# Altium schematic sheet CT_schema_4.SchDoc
size 235 x 277 mm
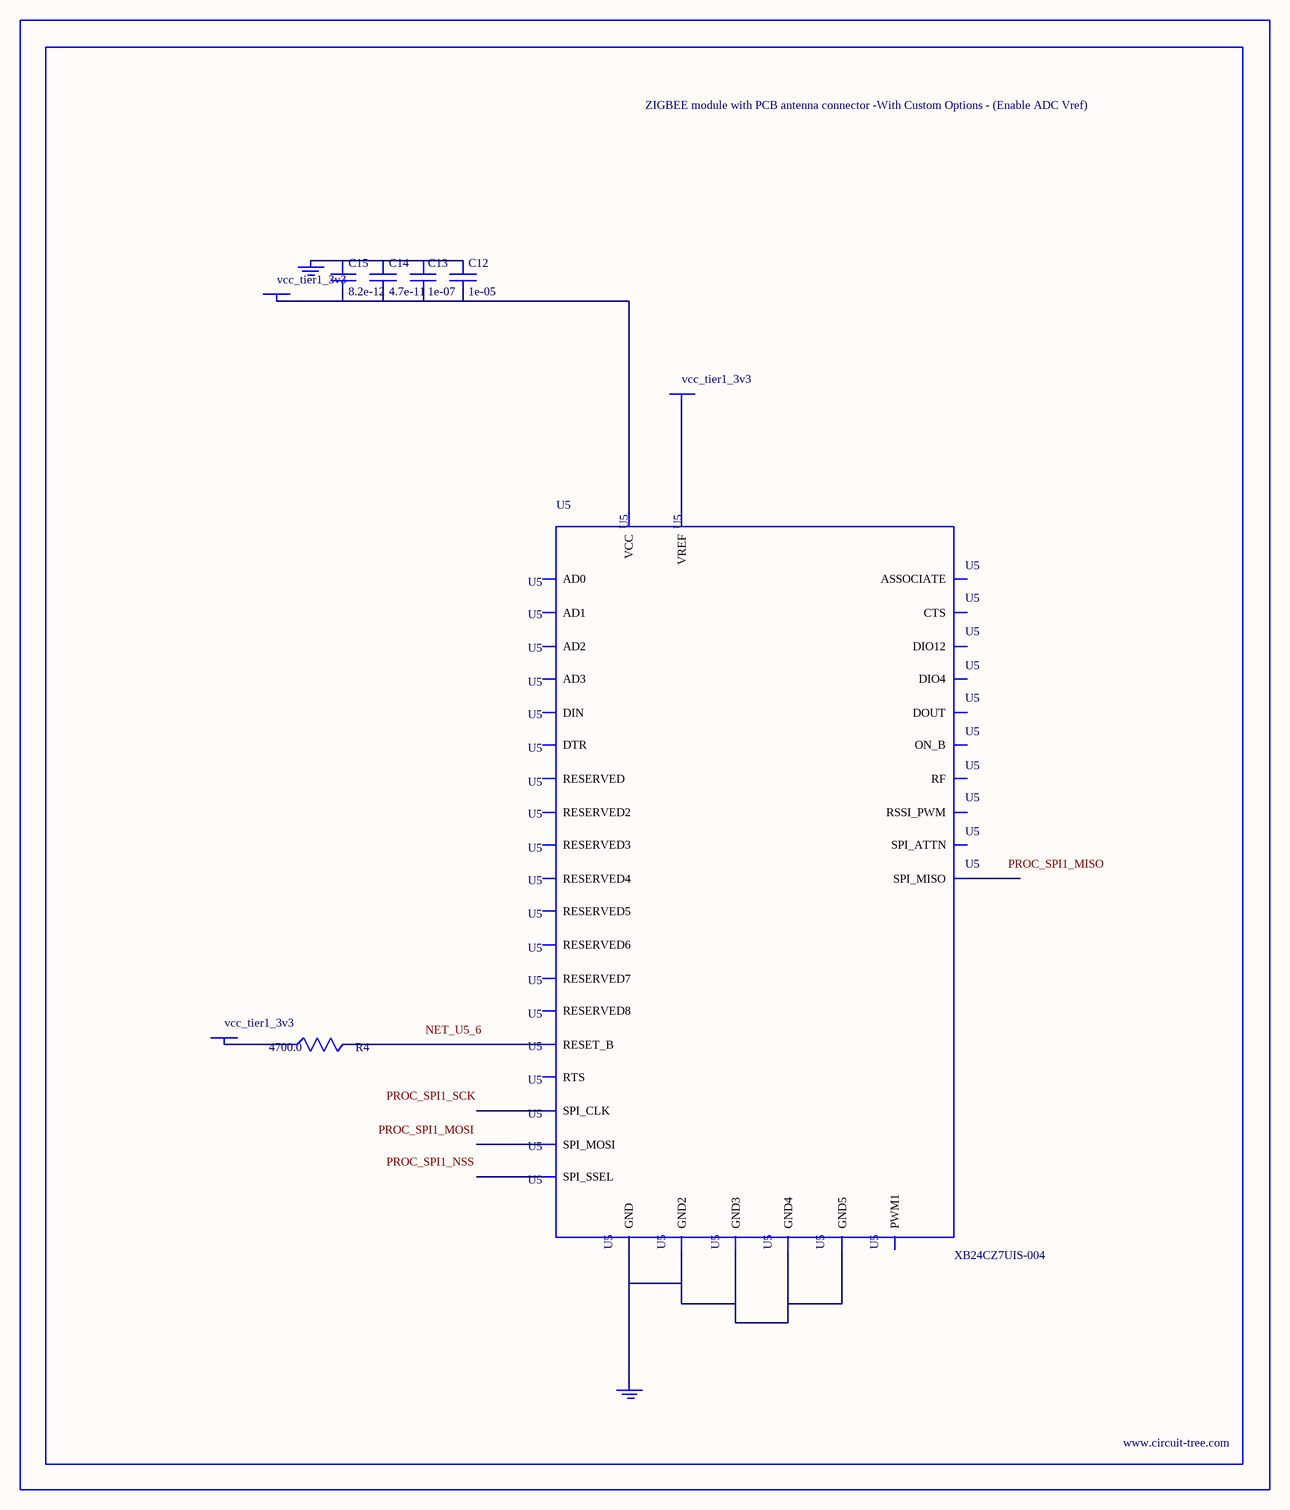
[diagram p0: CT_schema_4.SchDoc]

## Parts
BORDER3  (no value)
C12  1e-05  [C0805]
C13  1e-07  [C0402]
C14  4.7e-11  [C0402]
C15  8.2e-12  [C0603]
GND_INSTANCE_3_0  (no value)
GND_INSTANCE_3_1  (no value)
POWER_INSTANCE_3_0  vcc_tier1_3v3
POWER_INSTANCE_3_1  vcc_tier1_3v3
POWER_INSTANCE_3_2  vcc_tier1_3v3
R4  4700.0  [R0603]
U5  XB24CZ7UIS-004  [XB24CZ7UIS-004]

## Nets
NetC12_1: C12.1 C13.1 C14.1 C15.1 GND_INSTANCE_3_0.0(GND)
NetC12_2: C12.2 C13.2 C14.2 C15.2 POWER_INSTANCE_3_0.0(PWR) U5.2(VCC)
NetGND_INSTANCE_3_1_0: GND_INSTANCE_3_1.0(GND) U5.1(GND) U5.11(GND2) U5.13(GND3) U5.22(GND4) U5.35(GND5)
NetPOWER_INSTANCE_3_1_0: POWER_INSTANCE_3_1.0(PWR) R4.1
NetPOWER_INSTANCE_3_2_0: POWER_INSTANCE_3_2.0(PWR) U5.27(VREF)
NetR4_2: R4.2 U5.6(RESET_B)

Not connected (* = marked no-connect by the designer): U5 3(DOUT) 4(DIN) 5(DIO12) 7(RSSI_PWM) 8(PWM1) 9(RESERVED) 10(DTR) 12(SPI_ATTN) 14(SPI_CLK) 15(SPI_SSEL) 16(SPI_MOSI) 17(SPI_MISO) 18(RESERVED2) 19(RESERVED3) 20(RESERVED4) 21(RESERVED5) 23(RESERVED6) 24(DIO4) 25(CTS) 26(ON_B) 28(ASSOCIATE) 29(RTS) 30(AD3) 31(AD2) 32(AD1) 33(AD0) 34(RESERVED7) 36(RF) 37(RESERVED8)

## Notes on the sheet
- Labels drawn without touching a wire or pin: NET_U5_6, PROC_SPI1_MISO, PROC_SPI1_MOSI, PROC_SPI1_NSS, PROC_SPI1_SCK

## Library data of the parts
BORDER3 = BORDER_PAGE3
C12 = C0805C106K8RACTU
C13 = C0402C104K3RACTU
C14 = C0402C470K3RAC
C15 = 06035J8R2BBTTR
GND_INSTANCE_3_0 GND_INSTANCE_3_1 = GND
POWER_INSTANCE_3_0-POWER_INSTANCE_3_2 = PWR
R4 = RC0603JR-074K7L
